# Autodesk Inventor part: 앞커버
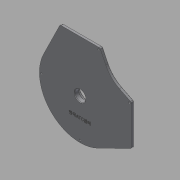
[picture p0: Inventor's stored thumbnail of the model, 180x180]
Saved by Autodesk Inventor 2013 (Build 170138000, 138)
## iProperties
Created: 2017-05
Part Number: 앞커버
Material: 일반
Document SubType Name: Modeling
Designer: mduedu
Density: 2.71 g/cm^3
Mass: 321.629 g
Surface Area: 500.043 cm^2
Volume: 118.682 cm^3
Author: mduedu
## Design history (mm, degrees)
sketch "스케치1"
  geometry: L1 (-71.801, 35.28)-(-40, 100); L2 (-40, 100)-(40, 100); L3 (40, 100)-(52.248, 75.073); L4 (35.28, 71.801)-(59.768, 59.768); L5 (100, 40)-(100, -40); L6 (100, -40)-(35.28, -71.801); L7 (75.073, 52.248)-(100, 40); L8 (59.768, 59.768)-(71.801, 35.28); L9 (33.075, -67.313)-(95, -36.886); L10 (95, -36.886)-(95, 36.886); L11 (95, 36.886)-(72.868, 47.76); L12 (47.76, 72.868)-(36.886, 95); L13 (36.886, 95)-(-36.886, 95); L14 (-36.886, 95)-(-67.313, 33.075); A1 r 80 centre (0, 0) between (71.801, 35.28) and (-71.801, 35.28); A2 r 80 centre (0, 0) between (35.28, -71.801) and (71.801, 35.28); A3 r 80 centre (0, 0) between (-71.801, 35.28) and (35.28, -71.801); A4 r 50 centre (97.123, 97.123) between (52.248, 75.073) and (75.073, 52.248); A5 r 55 centre (97.123, 97.123) between (47.76, 72.868) and (72.868, 47.76); A6 r 75 centre (0, 0) between (-67.313, 33.075) and (33.075, -67.313); 3 further points
  constraints: 29 end point, 15 tangent, 14 point on circle, 6 centre point, 2 midpoint, 2 perpendicular, 2 point on line, 1 coincident, 1 horizontal, 1 horizontal alignment, 1 vertical alignment, 6 other
  dimensions: "d0" = 160 diameter of A1; "d1" = 100 distance from line of L2 point (0, 0); "d2" = 100 distance from line of L5 point (0, 0); "d3" = 80 distance of L1.end L2.end; "d4" = 80 distance of L5.start L5.end; "d5" = 50 radius of A4; "d6" = 5 distance between parallel lines of L13 L2
extrude "돌출1" new body sketch "스케치1" distance "d7" = 5; taper "d8" = 0 deg
fillet "모깎기1" dims "d9" = 3
sketch "스케치2"
  geometry: C1 r 22 at (0, 0); 1 further point
  constraints: 1 centre point, 1 coincident
  dimensions: "d10" = 44 diameter of C1
extrude "돌출2" join sketch "스케치2" distance "d11" = 12.5; taper "d12" = 0 deg
sketch "스케치3"
  geometry: C1 r 18.5 at (0, 0); 1 further point
  constraints: 1 centre point, 1 coincident
  dimensions: "d13" = 37 diameter of C1
extrude "돌출3" cut sketch "스케치3" distance "d14" = 9; taper "d15" = 0 deg
hole "구멍1" diameter "d18" = 20; stored, may be unused: countersink angle "d22" = 90 deg, drill point angle "d24" = 118 deg; dims "d16" = 10, "d17" = 10, "d19" = 6, "d20" = 4, "d21" = 2, "d23" = 8
fillet "모깎기2" dims "d25" = 3
chamfer "모따기1" distance "d27" = 1; stored, may be unused: second distance "d28" = 2, angle "d29" = 45 deg
sketch "스케치4"
  geometry: 2 further points
  constraints: 1 vertical alignment, 1 other
  dimensions: "d30" = 35 distance of point (0, -35) point (0, 0)
feature "엠보싱1" sketch "스케치4" dims "d31" = 0.5, "d32" = 0
chamfer "모따기2" distance "d33" = 1; stored, may be unused: second distance "d34" = 2, angle "d35" = 45 deg
chamfer "모따기3" distance "d36" = 1; stored, may be unused: second distance "d37" = 2, angle "d38" = 45 deg
sketch "스케치5"
  geometry: L1 (18.989, -35.003)-(17.659, -35.003) reference; L2 (17.659, -35.003)-(17.659, -34.623) reference; L3 (17.659, -34.623)-(18.989, -34.623) reference; L4 (18.989, -34.623)-(18.989, -32.045) reference; L5 (18.989, -32.045)-(19.315, -32.045) reference; L6 (19.45, -32.31)-(19.45, -37.982) reference; L7 (19.45, -37.982)-(18.989, -37.982) reference; L8 (18.989, -37.982)-(18.989, -35.003) reference; L9 (-13.942, -34.352)-(-13.942, -34.746) reference; L10 (-13.942, -34.746)-(-15.061, -34.746) reference; L11 (-15.061, -34.746)-(-15.061, -36.489) reference; L12 (-15.061, -36.489)-(-15.536, -36.489) reference; L13 (-15.536, -36.489)-(-15.536, -31.998) reference; L14 (-15.536, -31.998)-(-15.231, -31.998) reference; L15 (-15.061, -32.263)-(-15.061, -34.352) reference; L16 (-15.061, -34.352)-(-13.942, -34.352) reference; L17 (-14.844, -37.439)-(-14.844, -37.819) reference; L18 (-14.844, -37.819)-(-19.193, -37.819) reference; L19 (-19.193, -37.819)-(-19.193, -36.191) reference; L20 (-19.193, -36.191)-(-18.84, -36.191) reference; L21 (-18.731, -36.408)-(-18.731, -37.439) reference; L22 (-18.731, -37.439)-(-14.844, -37.439) reference; L23 (-17.374, -32.575)-(-18.853, -32.575) reference; L24 (-18.853, -32.575)-(-18.853, -32.222) reference; L25 (-18.853, -32.222)-(-17.374, -32.222) reference; L26 (-17.374, -32.222)-(-17.374, -32.575) reference; L27 (-20.047, -33.382)-(-20.047, -33.029) reference; L28 (-20.047, -33.029)-(-16.282, -33.029) reference; L29 (-16.282, -33.029)-(-16.282, -33.382) reference; L30 (-16.282, -33.382)-(-20.047, -33.382) reference; L31 (-2.917, -37.615)-(-3.474, -36.089) reference; L32 (-3.474, -36.089)-(-5.726, -36.089) reference; L33 (-5.726, -36.089)-(-6.296, -37.615) reference; L34 (-6.296, -37.615)-(-6.777, -37.615) reference; L35 (-6.777, -37.615)-(-4.878, -32.615) reference; L36 (-4.878, -32.615)-(-4.335, -32.615) reference; L37 (-4.335, -32.615)-(-2.436, -37.615) reference; L38 (-2.436, -37.615)-(-2.917, -37.615) reference; L39 (-4.613, -33.104)-(-5.57, -35.675) reference; L40 (-5.57, -35.675)-(-3.636, -35.675) reference; L41 (-3.636, -35.675)-(-4.613, -33.104) reference; L42 (-10.095, -35.851)-(-8.284, -35.851) reference; L43 (-8.284, -35.851)-(-8.284, -37.975) reference; L44 (-8.284, -37.975)-(-8.745, -37.975) reference; L45 (-8.745, -37.975)-(-8.745, -36.225) reference; L46 (-8.745, -36.225)-(-12.578, -36.225) reference; L47 (-12.578, -36.225)-(-12.578, -35.851) reference; L48 (-12.578, -35.851)-(-10.55, -35.851) reference; L49 (-10.55, -35.851)-(-10.55, -34.63) reference; L50 (-10.55, -34.63)-(-13.311, -34.63) reference; L51 (-13.311, -34.63)-(-13.311, -34.257) reference; L52 (-13.311, -34.257)-(-8.942, -34.257) reference; L53 (-8.657, -32.588)-(-12.463, -32.588) reference; L54 (-12.463, -32.588)-(-12.463, -32.208) reference; L55 (-12.463, -32.208)-(-8.175, -32.208) reference; L56 (-8.446, -34.257)-(-7.307, -34.257) reference; L57 (-7.307, -34.257)-(-7.307, -34.63) reference; L58 (-7.307, -34.63)-(-10.095, -34.63) reference; L59 (-10.095, -34.63)-(-10.095, -35.851) reference; L60 (1.526, -32.615)-(1.526, -33.029) reference; L61 (1.526, -33.029)-(-0.034, -33.029) reference; L62 (-0.034, -33.029)-(-0.034, -37.615) reference; L63 (-0.034, -37.615)-(-0.488, -37.615) reference; L64 (-0.488, -37.615)-(-0.488, -33.029) reference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; C1 r 11 at (0, 0) reference; C2 r 4 at (-71, 0); C3 r 4 at (0, -71); C4 r 4 at (91, 34.394); C5 r 4 at (34.394, 91); A1 r 75 centre (0, 0) between (-67.313, 33.075) and (33.075, -67.313) reference; A2 r 3 centre (-35.017, 92) between (-35.017, 95) and (-37.71, 93.323) reference; A3 r 3 centre (35.017, 92) between (37.71, 93.323) and (35.017, 95) reference; A4 r 55 centre (97.123, 97.123) between (47.76, 72.868) and (72.868, 47.76) reference; A5 r 3 centre (92, 35.017) between (95, 35.017) and (93.323, 37.71) reference; A6 r 3 centre (92, -35.017) between (93.323, -37.71) and (95, -35.017) reference; A7 r 75 centre (0, 0) between (-67.313, 33.075) and (33.075, -67.313) reference; 66 further points
  constraints: 6 tangent, 4 centre point, 4 coincident, 3 equal radius, 1 horizontal alignment, 1 vertical alignment, 76 other
  dimensions: "d39" = 8 diameter of C2
  node "절단 모서리 투영1"
sketch "스케치6"
  geometry: 4 further points
  constraints: 4 other
hole "구멍2" sketch "스케치6" at (0, -71), (91, 34.394), (34.394, 91), (-71, 0) diameter "d40" = 3.4; stored, may be unused: countersink angle "d44" = 90 deg, drill point angle "d46" = 0 deg; dims "d41" = 6, "d42" = 4, "d43" = 2, "d45" = 8
node "솔리드1"
